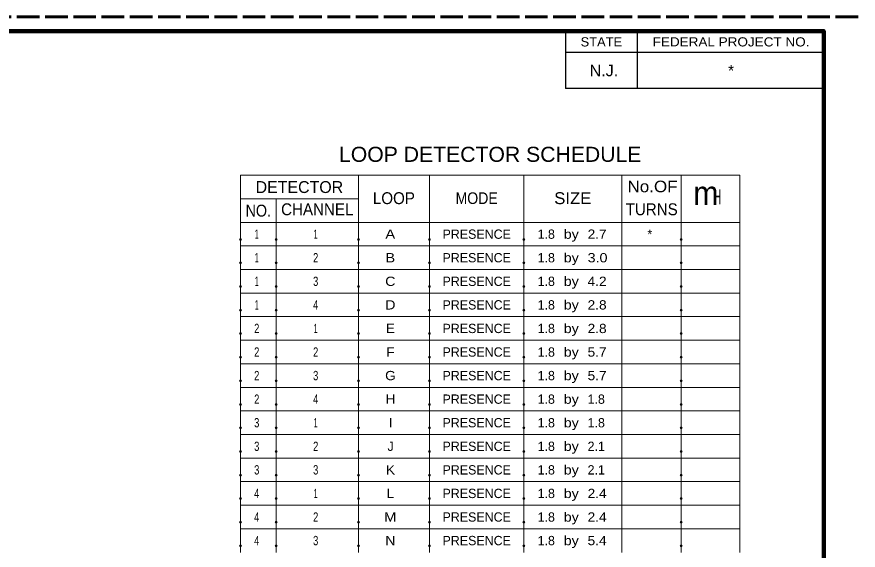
# Model space of a CAD drawing. Extents: x 168203 to 169863, y 223196 to 223870.
# Drawn here: x 169297 to 169364, y 223489.2 to 223531.7 of the extents above; entities that cross this region are included whole.
import ezdxf
from ezdxf.enums import TextEntityAlignment as Align

# ---------------------------------------------------------------- set-up
doc = ezdxf.new("R2010")
doc.units = 0
doc.header["$LTSCALE"] = 0.3
doc.header["$PDMODE"] = 32
doc.header["$PDSIZE"] = 0.15
doc.linetypes.add('LONG_DASHED', pattern=[7.5, 6, -1.5])
doc.layers.add('1', color=7, linetype='Continuous', lineweight=13)
doc.layers.add('9', color=7, linetype='Continuous', lineweight=13)

msp = doc.modelspace()

# ---------------------------------------------------------------- linework, layer by layer
at = {"layer": '1', "linetype": 'LONG_DASHED', "lineweight": 60}
msp.add_line((169364.0333, 223531.7489), (169095.8093, 223531.7489), dxfattribs=at)
at = {"layer": '1', "lineweight": 25}
for p, q in [((169340.7093, 223530.6089), (169340.7093, 223526.0369)), ((169346.4243, 223530.6089), (169346.4243, 223526.0369)), ((169361.2833, 223528.8944), (169340.7093, 223528.8944)), ((169361.2833, 223526.0369), (169340.7093, 223526.0369))]:
    msp.add_line(p, q, dxfattribs=at)
at = {"layer": '1', "lineweight": 158}
msp.add_lwpolyline([(169361.2833, 223368.6089), (169361.2833, 223530.6089), (169128.7833, 223530.6089), (169128.7833, 223368.6089)], close=True, dxfattribs=at)
at = {"layer": '9'}
for p, q in [((169314.8033, 223519.1173), (169314.8033, 223513.4787)), ((169314.8033, 223519.1173), (169354.6086, 223519.1173)), ((169324.2009, 223519.1173), (169324.2009, 223513.4787)), ((169329.8575, 223519.1173), (169329.8575, 223513.4787)), ((169337.3937, 223519.1173), (169337.3937, 223513.4787)), ((169345.1839, 223519.1173), (169345.1839, 223513.4787)), ((169349.9188, 223519.1173), (169349.9188, 223513.4787)), ((169354.6086, 223519.1173), (169354.6086, 223513.4787)), ((169314.8033, 223517.2378), (169324.1467, 223517.2378)), ((169317.6497, 223517.2378), (169317.6497, 223513.4787)), ((169314.8033, 223515.3583), (169354.6086, 223515.3583)), ((169314.8033, 223513.4787), (169354.6086, 223513.4787)), ((169314.8033, 223513.4787), (169314.8033, 223511.5992)), ((169317.6497, 223513.4787), (169317.6497, 223511.5992)), ((169324.2009, 223513.4787), (169324.2009, 223511.5992)), ((169329.8575, 223513.4787), (169329.8575, 223511.5992)), ((169337.3937, 223513.4787), (169337.3937, 223511.5992)), ((169345.1839, 223513.4787), (169345.1839, 223511.5992)), ((169349.9188, 223513.4787), (169349.9188, 223511.5992)), ((169354.6086, 223511.5992), (169354.6086, 223513.4787)), ((169314.8033, 223511.5992), (169354.6086, 223511.5992)), ((169314.8033, 223511.5992), (169314.8033, 223509.7197)), ((169317.6497, 223511.5992), (169317.6497, 223509.7197)), ((169324.2009, 223511.5992), (169324.2009, 223509.7197)), ((169329.8575, 223511.5992), (169329.8575, 223509.7197)), ((169337.3937, 223511.5992), (169337.3937, 223509.7197)), ((169345.1839, 223511.5992), (169345.1839, 223509.7197)), ((169349.9188, 223511.5992), (169349.9188, 223509.7197)), ((169354.6086, 223509.7197), (169354.6086, 223511.5992)), ((169314.8033, 223509.7197), (169354.6086, 223509.7197)), ((169314.8033, 223509.7197), (169314.8033, 223507.8402)), ((169317.6497, 223509.7197), (169317.6497, 223507.8402)), ((169324.2009, 223509.7197), (169324.2009, 223507.8402)), ((169329.8575, 223509.7197), (169329.8575, 223507.8402)), ((169337.3937, 223509.7197), (169337.3937, 223507.8402)), ((169345.1839, 223509.7197), (169345.1839, 223507.8402)), ((169349.9188, 223509.7197), (169349.9188, 223507.8402)), ((169354.6086, 223507.8402), (169354.6086, 223509.7197)), ((169314.8033, 223507.8402), (169354.6086, 223507.8402)), ((169314.8033, 223507.8402), (169314.8033, 223505.9607)), ((169317.6497, 223507.8402), (169317.6497, 223505.9607)), ((169324.2009, 223507.8402), (169324.2009, 223505.9607)), ((169329.8575, 223507.8402), (169329.8575, 223505.9607)), ((169337.3937, 223507.8402), (169337.3937, 223505.9607)), ((169345.1839, 223507.8402), (169345.1839, 223505.9607)), ((169349.9188, 223507.8402), (169349.9188, 223505.9607)), ((169354.6086, 223505.9607), (169354.6086, 223507.8402)), ((169314.8033, 223505.9607), (169354.6086, 223505.9607)), ((169314.8033, 223505.9607), (169314.8033, 223504.0812)), ((169317.6497, 223505.9607), (169317.6497, 223504.0812)), ((169324.2009, 223505.9607), (169324.2009, 223504.0812)), ((169329.8575, 223505.9607), (169329.8575, 223504.0812)), ((169337.3937, 223505.9607), (169337.3937, 223504.0812)), ((169345.1839, 223505.9607), (169345.1839, 223504.0812)), ((169349.9188, 223505.9607), (169349.9188, 223504.0812)), ((169354.6086, 223504.0812), (169354.6086, 223505.9607)), ((169314.8033, 223504.0812), (169354.6086, 223504.0812)), ((169314.8033, 223504.0812), (169314.8033, 223502.2017)), ((169317.6497, 223504.0812), (169317.6497, 223502.2017)), ((169324.2009, 223504.0812), (169324.2009, 223502.2017)), ((169329.8575, 223504.0812), (169329.8575, 223502.2017)), ((169337.3937, 223504.0812), (169337.3937, 223502.2017)), ((169345.1839, 223504.0812), (169345.1839, 223502.2017)), ((169349.9188, 223504.0812), (169349.9188, 223502.2017)), ((169354.6086, 223502.2017), (169354.6086, 223504.0812)), ((169314.8033, 223502.2017), (169354.6086, 223502.2017)), ((169314.8033, 223502.2017), (169314.8033, 223500.3222)), ((169317.6497, 223502.2017), (169317.6497, 223500.3222)), ((169324.2009, 223502.2017), (169324.2009, 223500.3222)), ((169329.8575, 223502.2017), (169329.8575, 223500.3222)), ((169337.3937, 223502.2017), (169337.3937, 223500.3222)), ((169345.1839, 223502.2017), (169345.1839, 223500.3222)), ((169349.9188, 223502.2017), (169349.9188, 223500.3222)), ((169354.6086, 223500.3222), (169354.6086, 223502.2017)), ((169314.8033, 223500.3222), (169354.6086, 223500.3222)), ((169314.8033, 223500.3222), (169314.8033, 223498.4427)), ((169317.6497, 223500.3222), (169317.6497, 223498.4427)), ((169324.2009, 223500.3222), (169324.2009, 223498.4427)), ((169329.8575, 223500.3222), (169329.8575, 223498.4427)), ((169337.3937, 223500.3222), (169337.3937, 223498.4427)), ((169345.1839, 223500.3222), (169345.1839, 223498.4427)), ((169349.9188, 223500.3222), (169349.9188, 223498.4427)), ((169354.6086, 223498.4427), (169354.6086, 223500.3222)), ((169314.8033, 223498.4427), (169354.6086, 223498.4427)), ((169314.8033, 223498.4427), (169314.8033, 223496.5632)), ((169317.6497, 223498.4427), (169317.6497, 223496.5632)), ((169324.2009, 223498.4427), (169324.2009, 223496.5632)), ((169329.8575, 223498.4427), (169329.8575, 223496.5632)), ((169337.3937, 223498.4427), (169337.3937, 223496.5632)), ((169345.1839, 223498.4427), (169345.1839, 223496.5632)), ((169349.9188, 223498.4427), (169349.9188, 223496.5632)), ((169354.6086, 223496.5632), (169354.6086, 223498.4427)), ((169314.8033, 223496.5632), (169354.6086, 223496.5632)), ((169314.8033, 223496.5632), (169314.8033, 223494.6837)), ((169317.6497, 223496.5632), (169317.6497, 223494.6837)), ((169324.2009, 223496.5632), (169324.2009, 223494.6837)), ((169329.8575, 223496.5632), (169329.8575, 223494.6837)), ((169337.3937, 223496.5632), (169337.3937, 223494.6837)), ((169345.1839, 223496.5632), (169345.1839, 223494.6837)), ((169349.9188, 223496.5632), (169349.9188, 223494.6837)), ((169354.6086, 223494.6837), (169354.6086, 223496.5632)), ((169314.8033, 223494.6837), (169354.6086, 223494.6837)), ((169314.8033, 223494.6837), (169314.8033, 223492.8042)), ((169317.6497, 223494.6837), (169317.6497, 223492.8042)), ((169324.2009, 223494.6837), (169324.2009, 223492.8042)), ((169329.8575, 223494.6837), (169329.8575, 223492.8042)), ((169337.3937, 223494.6837), (169337.3937, 223492.8042)), ((169345.1839, 223494.6837), (169345.1839, 223492.8042)), ((169349.9188, 223494.6837), (169349.9188, 223492.8042)), ((169354.6086, 223492.8042), (169354.6086, 223494.6837)), ((169314.8033, 223492.8042), (169354.6086, 223492.8042)), ((169314.8033, 223492.8042), (169314.8033, 223490.9247)), ((169317.6497, 223492.8042), (169317.6497, 223490.9247)), ((169324.2009, 223492.8042), (169324.2009, 223490.9247)), ((169329.8575, 223492.8042), (169329.8575, 223490.9247)), ((169337.3937, 223492.8042), (169337.3937, 223490.9247)), ((169345.1839, 223492.8042), (169345.1839, 223490.9247)), ((169349.9188, 223492.8042), (169349.9188, 223490.9247)), ((169354.6086, 223490.9247), (169354.6086, 223492.8042)), ((169314.8033, 223490.9247), (169354.6086, 223490.9247)), ((169314.8033, 223490.9247), (169314.8033, 223489.0452)), ((169317.6497, 223490.9247), (169317.6497, 223489.0452)), ((169324.2009, 223490.9247), (169324.2009, 223489.0452)), ((169329.8575, 223490.9247), (169329.8575, 223489.0452)), ((169337.3937, 223490.9247), (169337.3937, 223489.0452)), ((169345.1839, 223490.9247), (169345.1839, 223489.0452)), ((169349.9188, 223490.9247), (169349.9188, 223489.0452)), ((169354.6086, 223489.0452), (169354.6086, 223490.9247))]:
    msp.add_line(p, q, dxfattribs=at)
for p in [(169314.8033, 223514.0028), (169317.6497, 223514.0028), (169324.2009, 223514.0028), (169329.8575, 223514.0028), (169337.3937, 223514.0028), (169349.9188, 223514.0028), (169314.8033, 223512.1233), (169317.6497, 223512.1233), (169324.2009, 223512.1233), (169329.8575, 223512.1233), (169337.3937, 223512.1233), (169349.9188, 223512.1233), (169314.8033, 223510.2438), (169317.6497, 223510.2438), (169324.2009, 223510.2438), (169329.8575, 223510.2438), (169337.3937, 223510.2438), (169349.9188, 223510.2438), (169314.8033, 223508.3643), (169317.6497, 223508.3643), (169324.2009, 223508.3643), (169329.8575, 223508.3643), (169337.3937, 223508.3643), (169349.9188, 223508.3643), (169314.8033, 223506.4848), (169317.6497, 223506.4848), (169324.2009, 223506.4848), (169329.8575, 223506.4848), (169337.3937, 223506.4848), (169349.9188, 223506.4848), (169314.8033, 223504.6053), (169317.6497, 223504.6053), (169324.2009, 223504.6053), (169329.8575, 223504.6053), (169337.3937, 223504.6053), (169349.9188, 223504.6053), (169314.8033, 223502.7258), (169317.6497, 223502.7258), (169324.2009, 223502.7258), (169329.8575, 223502.7258), (169337.3937, 223502.7258), (169349.9188, 223502.7258), (169314.8033, 223500.8463), (169317.6497, 223500.8463), (169324.2009, 223500.8463), (169329.8575, 223500.8463), (169337.3937, 223500.8463), (169349.9188, 223500.8463), (169314.8033, 223498.9668), (169317.6497, 223498.9668), (169324.2009, 223498.9668), (169329.8575, 223498.9668), (169337.3937, 223498.9668), (169349.9188, 223498.9668), (169314.8033, 223497.0873), (169317.6497, 223497.0873), (169324.2009, 223497.0873), (169329.8575, 223497.0873), (169337.3937, 223497.0873), (169349.9188, 223497.0873), (169314.8033, 223495.2078), (169317.6497, 223495.2078), (169324.2009, 223495.2078), (169329.8575, 223495.2078), (169337.3937, 223495.2078), (169349.9188, 223495.2078), (169314.8033, 223493.3283), (169317.6497, 223493.3283), (169324.2009, 223493.3283), (169329.8575, 223493.3283), (169337.3937, 223493.3283), (169349.9188, 223493.3283), (169314.8033, 223491.4488), (169317.6497, 223491.4488), (169324.2009, 223491.4488), (169329.8575, 223491.4488), (169337.3937, 223491.4488), (169349.9188, 223491.4488), (169314.8033, 223489.5693), (169317.6497, 223489.5693), (169324.2009, 223489.5693), (169329.8575, 223489.5693), (169337.3937, 223489.5693), (169349.9188, 223489.5693)]:
    msp.add_point(p, dxfattribs=at)

# ---------------------------------------------------------------- texts
at = {"layer": '1'}
for s, height, width, p in [('STATE', 0.7315, 1.05, (169343.5668, 223529.3859)), ('FEDERAL PROJECT NO.', 0.7315, 1.1, (169353.9028, 223529.3859)), ('N.J.', 0.9144, 1.05, (169343.7648, 223527.0084))]:
    msp.add_text(s, height=height, dxfattribs=dict(at, width=width)).set_placement(p, align=Align.CENTER)
msp.add_text('*', height=0.9144, dxfattribs=at).set_placement((169353.9028, 223526.9999), align=Align.CENTER)
at = {"layer": '9'}
for s, height, width, p in [('LOOP DETECTOR SCHEDULE', 1.202, 1.05, (169334.7058, 223520.1836)), ('No.OF', 0.9217, 1.1, (169347.6431, 223517.7619)), ('LOOP', 0.9487, 0.95, (169327.0308, 223516.8131)), ('MODE', 0.9307, 0.9, (169333.6254, 223516.8221)), ('SIZE', 0.9488, 1.05, (169341.2871, 223516.8131)), ('m', 1.892, 0.95, (169351.8926, 223516.7498)), ('H', 1.202, 0.6, (169352.7806, 223516.795)), ('NO.', 0.9488, 0.9, (169316.2216, 223515.8191)), ('CHANNEL', 0.9487, 0.95, (169320.9218, 223515.9275)), ('TURNS', 0.9487, 0.95, (169347.5759, 223515.9275)), ('1', 0.741, 0.5, (169316.0985, 223514.048)), ('1', 0.741, 0.5, (169320.7973, 223514.048)), ('A ', 0.741, 1.2, (169326.9058, 223514.048)), ('by', 0.741, 1.15, (169341.1663, 223514.048)), ('1', 0.741, 0.5, (169316.0985, 223512.1685)), ('2', 0.741, 0.75, (169320.7973, 223512.1685)), ('B ', 0.741, 1.15, (169326.9059, 223512.1685)), ('by', 0.741, 1.15, (169341.1663, 223512.1685)), ('by', 0.741, 1.15, (169341.1663, 223510.289)), ('1', 0.741, 0.5, (169316.0985, 223510.289)), ('3', 0.741, 0.75, (169320.7973, 223510.289)), ('C ', 0.741, 1.15, (169326.9059, 223510.289)), ('1', 0.741, 0.5, (169316.0985, 223508.4095)), ('4', 0.741, 0.75, (169320.7973, 223508.4095)), ('D ', 0.741, 1.15, (169326.9059, 223508.4095)), ('by', 0.741, 1.15, (169341.1663, 223508.4095)), ('2', 0.741, 0.75, (169316.0985, 223506.53)), ('1', 0.741, 0.5, (169320.7973, 223506.53)), ('E ', 0.741, 1.1, (169326.9059, 223506.53)), ('by', 0.741, 1.15, (169341.1663, 223506.53)), ('2', 0.741, 0.75, (169316.0985, 223504.6505)), ('2', 0.741, 0.75, (169320.7973, 223504.6505)), ('F ', 0.741, 1.1, (169326.9059, 223504.6505)), ('by', 0.741, 1.15, (169341.1663, 223504.6505)), ('2', 0.741, 0.75, (169316.0985, 223502.771)), ('3', 0.741, 0.75, (169320.7973, 223502.771)), ('G ', 0.741, 1.1, (169326.9059, 223502.771)), ('by', 0.741, 1.15, (169341.1663, 223502.771)), ('by', 0.741, 1.15, (169341.1663, 223500.8915)), ('2', 0.741, 0.75, (169316.0985, 223500.8915)), ('4', 0.741, 0.75, (169320.7973, 223500.8915)), ('H ', 0.741, 1.1, (169326.9059, 223500.8915)), ('3', 0.741, 0.75, (169316.0985, 223499.012)), ('1', 0.741, 0.5, (169320.7973, 223499.012)), ('by', 0.741, 1.15, (169341.1663, 223499.012)), ('3', 0.741, 0.75, (169316.0985, 223497.1325)), ('2', 0.741, 0.75, (169320.7973, 223497.1325)), ('by', 0.741, 1.15, (169341.1663, 223497.1325)), ('3', 0.741, 0.75, (169316.0985, 223495.253)), ('3', 0.741, 0.75, (169320.7973, 223495.253)), ('K ', 0.741, 1.1, (169326.9059, 223495.253)), ('by', 0.741, 1.15, (169341.1663, 223495.253)), ('4', 0.741, 0.75, (169316.0985, 223493.3735)), ('1', 0.741, 0.5, (169320.7973, 223493.3735)), ('L ', 0.741, 1.1, (169326.9059, 223493.3735)), ('by', 0.741, 1.15, (169341.1663, 223493.3735)), ('4', 0.741, 0.75, (169316.0985, 223491.494)), ('2', 0.741, 0.75, (169320.7973, 223491.494)), ('M ', 0.741, 1.2, (169326.9058, 223491.494)), ('by', 0.741, 1.15, (169341.1663, 223491.494)), ('4', 0.741, 0.75, (169316.0985, 223489.6145)), ('3', 0.741, 0.75, (169320.7973, 223489.6145)), ('N ', 0.741, 1.15, (169326.9059, 223489.6145)), ('by', 0.741, 1.15, (169341.1663, 223489.6145))]:
    msp.add_text(s, height=height, dxfattribs=dict(at, width=width)).set_placement(p, align=Align.CENTER)
for s, height, p in [('DETECTOR', 0.9488, (169319.4991, 223517.6986)), ('PRESENCE', 0.741, (169333.6301, 223514.048)), ('*', 0.741, (169347.428, 223514.048)), ('PRESENCE', 0.741, (169333.6301, 223512.1685)), ('PRESENCE', 0.741, (169333.6301, 223510.289)), ('PRESENCE', 0.741, (169333.6301, 223508.4095)), ('PRESENCE', 0.741, (169333.6301, 223506.53)), ('PRESENCE', 0.741, (169333.6301, 223504.6505)), ('PRESENCE', 0.741, (169333.6301, 223502.771)), ('PRESENCE', 0.741, (169333.6301, 223500.8915)), ('I ', 0.741, (169326.9058, 223499.012)), ('PRESENCE', 0.741, (169333.6301, 223499.012)), ('J ', 0.741, (169326.9059, 223497.1325)), ('PRESENCE', 0.741, (169333.6301, 223497.1325)), ('PRESENCE', 0.741, (169333.6301, 223495.253)), ('PRESENCE', 0.741, (169333.6301, 223493.3735)), ('PRESENCE', 0.741, (169333.6301, 223491.494)), ('PRESENCE', 0.741, (169333.6301, 223489.6145))]:
    msp.add_text(s, height=height, dxfattribs=at).set_placement(p, align=Align.CENTER)
for p in [(169339.8622, 223514.048), (169339.8622, 223512.1685), (169339.8622, 223510.289), (169339.8622, 223508.4095), (169339.8622, 223506.53), (169339.8622, 223504.6505), (169339.8622, 223502.771), (169339.8622, 223500.8915), (169339.8622, 223499.012), (169339.8622, 223497.1325), (169339.8622, 223495.253), (169339.8622, 223493.3735), (169339.8622, 223491.494), (169339.8622, 223489.6145)]:
    msp.add_text('1.8', height=0.741, dxfattribs=at).set_placement(p, align=Align.RIGHT)
for s, width, p in [('2.7', 1.1, (169342.4685, 223514.048)), ('3.0', 1.15, (169342.4685, 223512.1685)), ('4.2', 1.1, (169342.4685, 223510.289)), ('2.8', 1.1, (169342.4685, 223508.4095)), ('2.8', 1.1, (169342.4685, 223506.53)), ('5.7', 1.1, (169342.4685, 223504.6505)), ('5.7', 1.1, (169342.4685, 223502.771)), ('2.4', 1.1, (169342.4685, 223493.3735)), ('2.4', 1.1, (169342.4685, 223491.494)), ('5.4', 1.1, (169342.4685, 223489.6145))]:
    msp.add_text(s, height=0.741, dxfattribs=dict(at, width=width)).set_placement(p)
for s, p in [('1.8', (169342.4685, 223500.8915)), ('1.8', (169342.4685, 223499.012)), ('2.1', (169342.4685, 223497.1325)), ('2.1', (169342.4685, 223495.253))]:
    msp.add_text(s, height=0.741, dxfattribs=at).set_placement(p)

doc.saveas('drawing.dxf')
